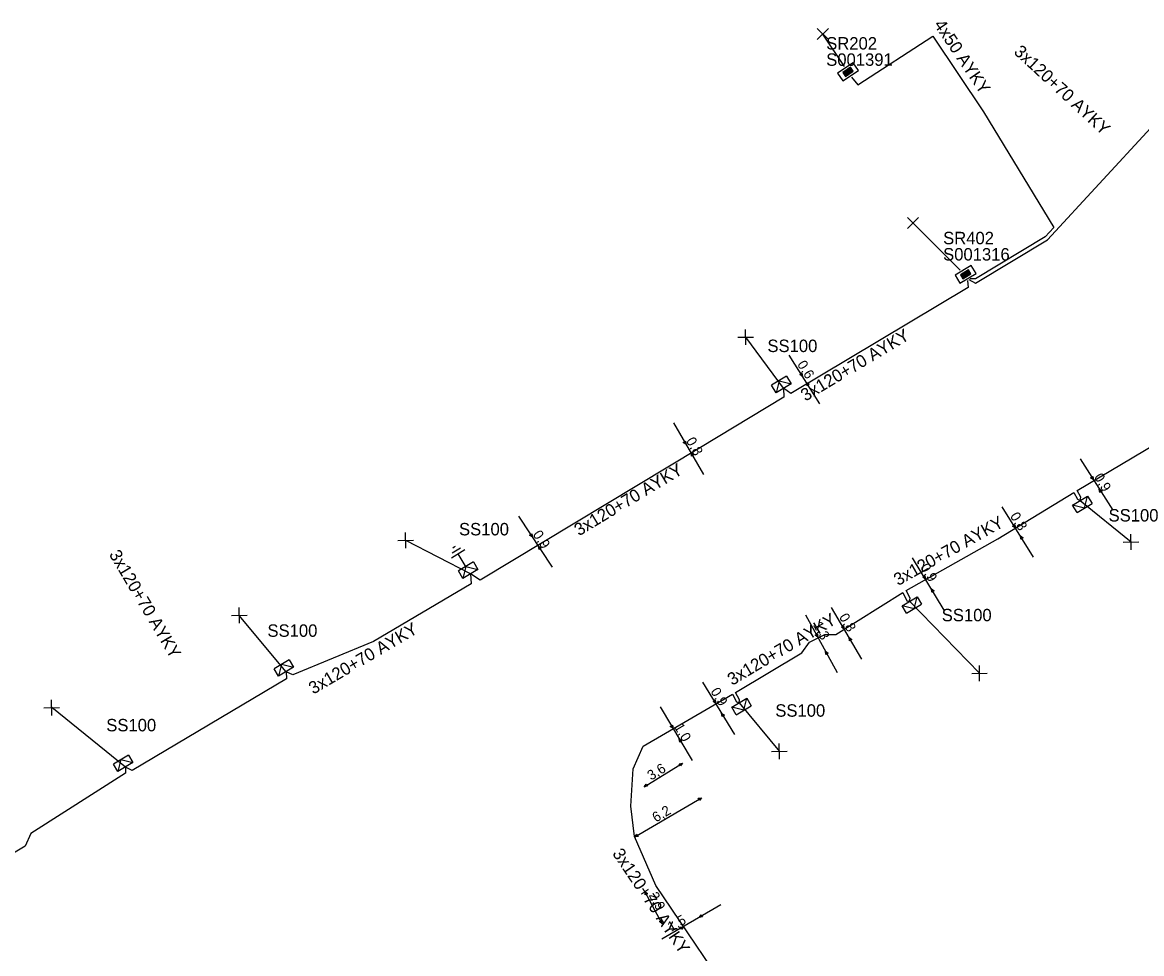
# Model space of a CAD drawing. Extents: x -762500 to -761285, y -1155006 to -1154135.
# Drawn here: x -761909.8 to -761820.3, y -1154763.7 to -1154689.2 of the extents above; entities that cross this region are included whole.
import ezdxf

# ---------------------------------------------------------------- set-up
doc = ezdxf.new("R2010")
doc.units = 0
for name, color, linetype in [('Vrstva 15', 7, 'Continuous'), ('Vrstva 28', 7, 'Continuous'), ('Vrstva 29', 7, 'Continuous'), ('Vrstva 30', 7, 'Continuous'), ('Vrstva 31', 7, 'Continuous'), ('Vrstva 33', 7, 'Continuous'), ('Vrstva 34', 7, 'Continuous'), ('Vrstva 40', 7, 'Continuous'), ('Vrstva 5', 7, 'Continuous'), ('Vrstva 59', 7, 'Continuous'), ('Vrstva 6', 7, 'Continuous')]:
    doc.layers.add(name, color=color, linetype=linetype)

msp = doc.modelspace()

# ---------------------------------------------------------------- linework, layer by layer
at = {"layer": 'Vrstva 15'}
for points in [[(-761875.473, -1154732.014), (-761874.402, -1154731.37)], [(-761875.426, -1154731.624), (-761874.751, -1154731.219)], [(-761875.373, -1154731.225), (-761875.259, -1154731.156)], [(-761875.259, -1154731.156), (-761875.15, -1154731.09)], [(-761874.294, -1154732.764), (-761874.938, -1154731.692)]]:
    msp.add_lwpolyline(points, dxfattribs=at)
at = {"layer": 'Vrstva 28'}
for points in [[(-761843.357, -1154692.433), (-761844.601, -1154693.271)], [(-761844.182, -1154693.893), (-761842.938, -1154693.054)], [(-761843.56, -1154692.797), (-761844.177, -1154693.213)], [(-761844.177, -1154693.213), (-761843.966, -1154693.527)], [(-761843.573, -1154692.863), (-761844.112, -1154693.226)], [(-761844.112, -1154693.226), (-761843.953, -1154693.461)], [(-761843.586, -1154692.929), (-761844.046, -1154693.239)], [(-761844.046, -1154693.239), (-761843.94, -1154693.396)], [(-761843.598, -1154692.994), (-761843.98, -1154693.252)], [(-761843.98, -1154693.252), (-761843.928, -1154693.33)], [(-761843.966, -1154693.527), (-761843.349, -1154693.111)], [(-761843.953, -1154693.461), (-761843.414, -1154693.098)], [(-761843.94, -1154693.396), (-761843.48, -1154693.085)], [(-761843.928, -1154693.33), (-761843.546, -1154693.072)], [(-761843.606, -1154693.056), (-761843.92, -1154693.268)], [(-761843.546, -1154693.072), (-761843.598, -1154692.994)], [(-761843.48, -1154693.085), (-761843.586, -1154692.929)], [(-761843.414, -1154693.098), (-761843.573, -1154692.863)], [(-761843.349, -1154693.111), (-761843.56, -1154692.797)], [(-761842.938, -1154693.054), (-761843.357, -1154692.433)], [(-761844.601, -1154693.271), (-761844.182, -1154693.893)], [(-761833.914, -1154708.645), (-761835.199, -1154709.417)], [(-761834.813, -1154710.06), (-761833.527, -1154709.288)], [(-761834.135, -1154708.998), (-761834.773, -1154709.382)], [(-761834.151, -1154709.063), (-761834.708, -1154709.398)], [(-761834.168, -1154709.128), (-761834.643, -1154709.414)], [(-761834.184, -1154709.193), (-761834.579, -1154709.43)], [(-761834.578, -1154709.705), (-761833.941, -1154709.322)], [(-761834.562, -1154709.641), (-761834.005, -1154709.306)], [(-761834.546, -1154709.576), (-761834.07, -1154709.29)], [(-761834.53, -1154709.511), (-761834.135, -1154709.274)], [(-761834.195, -1154709.255), (-761834.519, -1154709.449)], [(-761834.135, -1154709.274), (-761834.184, -1154709.193)], [(-761834.07, -1154709.29), (-761834.168, -1154709.128)], [(-761834.005, -1154709.306), (-761834.151, -1154709.063)], [(-761833.941, -1154709.322), (-761834.135, -1154708.998)], [(-761833.527, -1154709.288), (-761833.914, -1154708.645)], [(-761835.199, -1154709.417), (-761834.813, -1154710.06)], [(-761834.773, -1154709.382), (-761834.578, -1154709.705)], [(-761834.708, -1154709.398), (-761834.562, -1154709.641)], [(-761834.643, -1154709.414), (-761834.546, -1154709.576)], [(-761834.579, -1154709.43), (-761834.53, -1154709.511)]]:
    msp.add_lwpolyline(points, dxfattribs=at)
at = {"layer": 'Vrstva 31'}
for points in [[(-761848.678, -1154717.498), (-761849.878, -1154718.219)], [(-761848.678, -1154717.498), (-761848.318, -1154718.098), (-761849.518, -1154718.819), (-761849.878, -1154718.219)], [(-761849.278, -1154717.858), (-761849.518, -1154718.819)], [(-761849.278, -1154717.858), (-761848.318, -1154718.098)], [(-761825.452, -1154728.403), (-761825.812, -1154727.803), (-761824.612, -1154727.082), (-761824.252, -1154727.682)], [(-761824.852, -1154728.042), (-761824.612, -1154727.082)], [(-761824.852, -1154728.042), (-761825.812, -1154727.803)], [(-761825.452, -1154728.403), (-761824.252, -1154727.682)], [(-761873.718, -1154732.348), (-761874.918, -1154733.069)], [(-761873.718, -1154732.348), (-761873.357, -1154732.948), (-761874.558, -1154733.669), (-761874.918, -1154733.069)], [(-761874.318, -1154732.709), (-761874.558, -1154733.669)], [(-761874.318, -1154732.709), (-761873.357, -1154732.948)], [(-761839.082, -1154736.462), (-761839.442, -1154735.862), (-761838.242, -1154735.141), (-761837.882, -1154735.741)], [(-761838.482, -1154736.102), (-761838.242, -1154735.141)], [(-761838.482, -1154736.102), (-761839.442, -1154735.862)], [(-761839.082, -1154736.462), (-761837.882, -1154735.741)], [(-761888.458, -1154740.168), (-761889.658, -1154740.889)], [(-761888.458, -1154740.168), (-761888.098, -1154740.768), (-761889.298, -1154741.489), (-761889.658, -1154740.889)], [(-761889.058, -1154740.528), (-761889.298, -1154741.489)], [(-761889.058, -1154740.528), (-761888.098, -1154740.768)], [(-761852.702, -1154744.572), (-761853.062, -1154743.972), (-761851.862, -1154743.251), (-761851.502, -1154743.851)], [(-761852.102, -1154744.212), (-761851.862, -1154743.251)], [(-761852.102, -1154744.212), (-761853.062, -1154743.972)], [(-761852.702, -1154744.572), (-761851.502, -1154743.851)], [(-761901.308, -1154747.798), (-761902.508, -1154748.519)], [(-761901.308, -1154747.798), (-761900.947, -1154748.398), (-761902.147, -1154749.119), (-761902.508, -1154748.519)], [(-761901.908, -1154748.158), (-761902.147, -1154749.119)], [(-761901.908, -1154748.158), (-761900.947, -1154748.398)]]:
    msp.add_lwpolyline(points, dxfattribs=at)
at = {"layer": 'Vrstva 34'}
for points in [[(-761846.222, -1154689.698), (-761845.338, -1154690.582)], [(-761846.222, -1154690.582), (-761845.338, -1154689.698)], [(-761839.002, -1154704.808), (-761838.118, -1154705.692)], [(-761839.002, -1154705.692), (-761838.118, -1154704.808)], [(-761851.929, -1154715.005), (-761851.951, -1154713.755)], [(-761852.565, -1154714.391), (-761851.315, -1154714.369)], [(-761879.755, -1154730.641), (-761878.505, -1154730.619)], [(-761879.119, -1154731.255), (-761879.141, -1154730.005)], [(-761821.755, -1154730.761), (-761820.505, -1154730.739)], [(-761821.119, -1154731.375), (-761821.141, -1154730.125)], [(-761892.429, -1154737.255), (-761892.451, -1154736.005)], [(-761893.065, -1154736.641), (-761891.815, -1154736.619)], [(-761833.239, -1154741.875), (-761833.261, -1154740.625)], [(-761833.875, -1154741.261), (-761832.625, -1154741.239)], [(-761907.429, -1154744.625), (-761907.451, -1154743.375)], [(-761908.065, -1154744.011), (-761906.815, -1154743.989)], [(-761849.239, -1154748.125), (-761849.261, -1154746.875)], [(-761849.875, -1154747.511), (-761848.625, -1154747.489)]]:
    msp.add_lwpolyline(points, dxfattribs=at)
at = {"layer": 'Vrstva 40'}
for points in [[(-761846.02, -1154719.7), (-761848.47, -1154715.82)], [(-761857.72, -1154721.22), (-761855.32, -1154725.37)], [(-761825.21, -1154724.1), (-761822.59, -1154728.22)], [(-761828.92, -1154731.98), (-761831.44, -1154727.94)], [(-761870.11, -1154728.69), (-761867.42, -1154732.77)], [(-761836.07, -1154736.22), (-761838.6, -1154732.02)], [(-761842.67, -1154740.12), (-761845.09, -1154736)], [(-761844.61, -1154741.23), (-761847.14, -1154736.62)], [(-761852.82, -1154746.14), (-761855.38, -1154741.96)], [(-761858.78, -1154743.95), (-761856.24, -1154748.23)], [(-761860.06, -1154750.33), (-761857.01, -1154748.45)], [(-761860.82, -1154754.34), (-761855.49, -1154751.21)], [(-761858.64, -1154761.28), (-761860.02, -1154758.7)], [(-761853.93, -1154759.77), (-761858.66, -1154762.53)]]:
    msp.add_lwpolyline(points, dxfattribs=at)
for points in [[(-761847.398, -1154717.512), (-761847.621, -1154717.36), (-761847.446, -1154717.247)], [(-761847.092, -1154717.998), (-761846.868, -1154718.15), (-761847.044, -1154718.263)], [(-761856.719, -1154722.952), (-761856.937, -1154722.793), (-761856.757, -1154722.685)], [(-761856.321, -1154723.638), (-761856.103, -1154723.797), (-761856.283, -1154723.905)], [(-761824.139, -1154725.792), (-761824.362, -1154725.64), (-761824.187, -1154725.526)], [(-761823.671, -1154726.527), (-761823.448, -1154726.679), (-761823.624, -1154726.793)], [(-761830.379, -1154729.642), (-761830.602, -1154729.491), (-761830.427, -1154729.377)], [(-761869.009, -1154730.362), (-761869.234, -1154730.215), (-761869.061, -1154730.098)], [(-761829.981, -1154730.278), (-761829.758, -1154730.429), (-761829.933, -1154730.543)], [(-761868.521, -1154731.098), (-761868.296, -1154731.245), (-761868.469, -1154731.362)], [(-761837.569, -1154733.732), (-761837.789, -1154733.577), (-761837.612, -1154733.466)], [(-761837.101, -1154734.508), (-761836.881, -1154734.663), (-761837.058, -1154734.774)], [(-761844.079, -1154737.722), (-761844.297, -1154737.563), (-761844.117, -1154737.455)], [(-761846.179, -1154738.372), (-761846.391, -1154738.206), (-761846.208, -1154738.104)], [(-761843.681, -1154738.398), (-761843.463, -1154738.557), (-761843.643, -1154738.665)], [(-761845.571, -1154739.478), (-761845.359, -1154739.644), (-761845.542, -1154739.746)], [(-761854.338, -1154743.672), (-761854.559, -1154743.516), (-761854.382, -1154743.406)], [(-761853.871, -1154744.437), (-761853.65, -1154744.593), (-761853.828, -1154744.704)], [(-761857.759, -1154745.672), (-761857.976, -1154745.513), (-761857.797, -1154745.405)], [(-761857.261, -1154746.508), (-761857.044, -1154746.667), (-761857.223, -1154746.775)], [(-761857.008, -1154748.449), (-761857.163, -1154748.669), (-761857.274, -1154748.492)], [(-761860.063, -1154750.331), (-761859.907, -1154750.111), (-761859.796, -1154750.288)], [(-761855.488, -1154751.209), (-761855.647, -1154751.426), (-761855.754, -1154751.247)], [(-761860.822, -1154754.341), (-761860.663, -1154754.123), (-761860.555, -1154754.303)], [(-761860.021, -1154758.698), (-761859.809, -1154758.865), (-761859.992, -1154758.966)], [(-761858.639, -1154761.283), (-761858.851, -1154761.116), (-761858.668, -1154761.015)], [(-761855.662, -1154760.781), (-761855.503, -1154760.563), (-761855.395, -1154760.743)], [(-761856.928, -1154761.519), (-761857.087, -1154761.736), (-761857.195, -1154761.557)]]:
    msp.add_lwpolyline(points, close=True, dxfattribs=at)
at = {"layer": 'Vrstva 5'}
for points in [[(-761843.48, -1154693.58), (-761842.98, -1154694.2), (-761836.99, -1154690.32), (-761832.92, -1154696.36), (-761827.3, -1154705.6), (-761828, -1154706.35), (-761833.56, -1154709.71), (-761833.99, -1154709.72)], [(-761834.1, -1154709.78), (-761833.57, -1154710.06), (-761827.8, -1154706.59), (-761819.55, -1154697.65), (-761819.23, -1154697.53), (-761819.28, -1154698.14), (-761815.44, -1154703.86), (-761812.64, -1154704.83), (-761792.79, -1154694.24), (-761792.75, -1154693.81)], [(-761834.21, -1154709.85), (-761834.16, -1154710.4), (-761848.34, -1154718.88), (-761848.92, -1154718.46)], [(-761848.92, -1154718.46), (-761848.9, -1154719.18), (-761855.55, -1154723.19), (-761873.18, -1154733.8), (-761873.96, -1154733.31)], [(-761825.21, -1154727.44), (-761825.16, -1154727.17), (-761825.43, -1154726.65), (-761816.51, -1154721.34), (-761813.58, -1154720.25), (-761810.39, -1154725.58), (-761808.75, -1154726.29), (-761804.74, -1154732.32), (-761801.12, -1154738.26), (-761801.36, -1154738.52), (-761800.98, -1154738.53), (-761796.81, -1154745.62), (-761793.41, -1154751.37), (-761793.57, -1154751.43)], [(-761852.06, -1154768.68), (-761859.12, -1154758.22), (-761860.83, -1154754.31), (-761861.13, -1154751.88), (-761860.94, -1154748.91), (-761860.15, -1154747.09), (-761853.01, -1154742.93), (-761852.67, -1154743.54), (-761852.46, -1154743.61), (-761852.43, -1154743.37), (-761852.75, -1154742.79), (-761847.45, -1154739.62), (-761846.85, -1154738.78), (-761845.63, -1154738.15), (-761844.75, -1154738.15), (-761839.38, -1154734.8), (-761839.05, -1154735.45), (-761838.84, -1154735.5), (-761838.79, -1154735.25), (-761839.12, -1154734.64), (-761831.78, -1154730.51), (-761825.7, -1154726.81), (-761825.42, -1154727.34), (-761825.21, -1154727.44)], [(-761873.96, -1154733.31), (-761873.9, -1154734.11), (-761881.71, -1154738.72), (-761888.15, -1154741.37), (-761888.7, -1154741.13), (-761888.66, -1154741.7), (-761901, -1154749.02), (-761901.55, -1154748.76), (-761901.53, -1154749.24), (-761909.11, -1154754.08), (-761909.56, -1154755.09), (-761914.55, -1154758.07), (-761915.11, -1154757.81)]]:
    msp.add_lwpolyline(points, dxfattribs=at)
at = {"layer": 'Vrstva 59'}
for points in [[(-761844.05, -1154692.74), (-761845.78, -1154690.14)], [(-761834.81, -1154709.03), (-761838.56, -1154705.25)], [(-761848.92, -1154718.46), (-761851.94, -1154714.38)], [(-761825.21, -1154727.44), (-761821.13, -1154730.75)], [(-761873.96, -1154733.31), (-761879.13, -1154730.63)], [(-761838.84, -1154735.5), (-761833.25, -1154741.25)], [(-761888.7, -1154741.13), (-761892.44, -1154736.63)], [(-761901.55, -1154748.76), (-761907.44, -1154744)], [(-761852.46, -1154743.61), (-761849.25, -1154747.5)]]:
    msp.add_lwpolyline(points, dxfattribs=at)

# ---------------------------------------------------------------- texts
at = {"layer": 'Vrstva 29'}
for s, p in [('S001391', (-761845.51, -1154692.68)), ('S001316', (-761836.16, -1154708.25))]:
    msp.add_text(s, height=0.9943, dxfattribs=at).set_placement(p)
at = {"layer": 'Vrstva 30'}
for s, p in [('SR202', (-761845.51, -1154691.38)), ('SR402', (-761836.16, -1154706.95))]:
    msp.add_text(s, height=0.9943, dxfattribs=at).set_placement(p)
at = {"layer": 'Vrstva 33'}
for p in [(-761850.21, -1154715.57), (-761822.93, -1154729.12), (-761874.87, -1154730.23), (-761836.27, -1154737.1), (-761890.19, -1154738.34), (-761849.58, -1154744.73), (-761903.08, -1154745.9)]:
    msp.add_text('SS100', height=0.9943, dxfattribs=at).set_placement(p)
at = {"layer": 'Vrstva 40'}
for s, rotation, p in [('0,6', 302.21941, (-761847.86, -1154716.55)), ('0,8', 300.10385, (-761856.75, -1154722.66)), ('0,9', 302.42061, (-761824.13, -1154725.57)), ('0,8', 302.00784, (-761830.84, -1154728.68)), ('0,9', 303.51213, (-761869.01, -1154730.15)), ('0,9', 301.06933, (-761838.02, -1154732.76)), ('0,8', 300.46864, (-761844.51, -1154736.75)), ('1,3', 298.79261, (-761846.59, -1154737.38)), ('0,9', 301.40172, (-761854.79, -1154742.7)), ('1,0', 300.76089, (-761857.7, -1154745.54)), ('3,6', 31.64955, (-761859.51, -1154749.85)), ('6,2', 30.42333, (-761859.13, -1154753.2)), ('2,9', 298.05012, (-761859.72, -1154759)), ('1,5', 30.22834, (-761857.91, -1154761.95))]:
    msp.add_text(s, height=0.7954, rotation=rotation, dxfattribs=at).set_placement(p)
at = {"layer": 'Vrstva 6'}
for s, height, rotation, p in [('4x50 AYKY', 0.9943, 303.95866, (-761836.94, -1154689.39)), ('3x120+70 AYKY', 0.99429, 317.27224, (-761830.57, -1154691.65)), ('3x120+70 AYKY', 0.99429, 30.87933, (-761847.17, -1154719.54)), ('3x120+70 AYKY', 0.99429, 31.02536, (-761865.28, -1154730.31)), ('3x120+70 AYKY', 0.99429, 29.38111, (-761839.76, -1154734.29)), ('3x120+70 AYKY', 0.99429, 300.6597, (-761902.89, -1154731.75)), ('3x120+70 AYKY', 0.99429, 30.86507, (-761853.03, -1154742.27)), ('3x120+70 AYKY', 0.99429, 30.52999, (-761886.52, -1154742.97)), ('3x120+70 AYKY', 0.99428, 304.00749, (-761862.65, -1154755.67))]:
    msp.add_text(s, height=height, rotation=rotation, dxfattribs=at).set_placement(p)

doc.saveas('drawing.dxf')
